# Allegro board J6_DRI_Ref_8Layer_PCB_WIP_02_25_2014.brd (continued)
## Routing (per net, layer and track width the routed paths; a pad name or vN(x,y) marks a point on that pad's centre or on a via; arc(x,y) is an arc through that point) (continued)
H_DDR2_A14: length 84
  TOP w0.102: U52.R22 v1(67.08,53.27)
  TOP w0.127: TP2MB25.1 96.7,19.1 97.16,19.1 97.38,19.33 U69.N7 ; TP2MA25.1 82.35,19.1 82.8,19.1 83.03,19.33 U68.N7 ; RN7.4 v1(104.3,19.07)
  L3-SIGNAL w0.114: v1(104.3,19.07) 103.64,19.07 103.25,19.46 102.61,19.46 102.28,19.12 96.68,19.12 TP2MB25.1 95.17,19.51 94.97,19.71 93.57,19.71 93.45,19.59 92.18,19.59 91.71,19.12 82.33,19.12 TP2MA25.1
  L6-SIGNAL w0.102: v2(70.26,24.46) 72.34,24.46 72.85,23.95 72.85,23.24 73.08,23.01 74.62,23.01 75.57,22.06 75.57,21.23 75.72,21.08 76.61,21.08 76.72,20.98 76.72,20.75 76.82,20.65 77.02,20.65 77.12,20.75 77.12,20.98 77.22,21.08 78.37,21.08 78.66,20.78 80.04,20.78 81.31,19.51 TP2MA25.1
  BOTTOM w0.102: 67.04,50.17 66.98,50.1 66.98,48.76 66.8,48.58
  BOTTOM w0.127: 66.8,48.58 66.8,47.08 66.62,46.9 66.62,41.28 67.77,40.13 67.77,38.64 70.82,35.59 70.82,32.46 70.69,32.34 70.43,32.34 70.31,32.21 70.31,31.45 70.43,31.32 70.69,31.32 70.82,31.19 70.82,29.03 70.69,28.91 70.38,28.91 70.26,28.78 v2(70.26,24.46) ; v1(67.08,53.27) 67.08,52.66 67.04,52.62 67.04,50.17 ; TP2MB25.1 95.4,19.51 94.18,20.73 U115.N7 ; U116.N7 79.83,20.73 81.05,19.51 TP2MA25.1
H_DDR2_A15: length 78.5
  TOP w0.102: U52.U22 v1(65.53,53.25)
  TOP w0.127: TP2MA12.1 81.57,24.32 82.97,24.32 U68.J7 ; TP2MB12.1 95.92,24.32 97.32,24.32 U69.J7 ; RN3.3 v1(103.66,26.5)
  L3-SIGNAL w0.114: v1(65.53,53.25) 65.94,52.84 65.94,50.61 65.7,50.37 65.43,50.37 65.18,50.12 65.18,48.95 65.43,48.69 65.43,40.72 65.3,40.59 64.52,40.59 64.19,40.26 64.19,37.19 64.41,36.97 64.41,36.11 64.16,35.86 64.16,35.31 64.39,35.08 64.39,34.32 64.55,34.16 64.71,34.16 64.88,34.33 65.05,34.33 65.21,34.17 65.21,34.01 65.03,33.84 65.03,33.68 65.48,33.23 65.48,32.6 65.67,32.41 66.22,32.41 66.4,32.24 66.4,31.3 67.02,30.67 68.76,30.67 71.75,27.68 71.75,25.91 73.46,24.21 73.79,24.21 74.3,23.7 77.25,23.7 77.5,23.46 80.64,23.46 80.89,23.71 81.24,23.71 81.56,24.03 TP2MA12.1 81.89,24.34 81.9,24.33 82.68,24.33 83.03,24.67 84.68,24.67 85.11,25.1 92.02,25.1 92.58,24.54 95.2,24.54 95.4,24.34 TP2MB12.1 96.29,24.34 96.3,24.33 100.22,24.33 102.39,26.5 v1(103.66,26.5)
  BOTTOM w0.127: TP2MB12.1 95.55,24.34 95.34,24.55 94.48,24.55 U115.J7 ; U116.J7 80.1,24.53 81.01,24.53 81.2,24.34 TP2MA12.1
H_DDR2_BA0: length 82.3
  TOP w0.102: U52.U23 v1(65.52,52.45)
  TOP w0.127: U68.J2 79.43,24.65 80.23,24.65 TP2MA10.1 ; U69.J2 93.78,24.65 94.58,24.65 TP2MB10.1
  L3-SIGNAL w0.114: v2(65.86,33.61) 68.78,33.61 69.1,33.29 70.75,33.29 71.2,32.84 73.23,32.84 73.36,32.72 73.36,32.16 73.23,32.04 72.84,32.04 72.72,31.92 72.72,31.75 72.84,31.63 73.25,31.63 73.36,31.53 73.36,31.32 73.25,31.22 73.09,31.22 72.97,31.1 72.97,30.94 73.09,30.82 73.25,30.82 73.36,30.71 73.36,30.51 73.25,30.41 72.92,30.41 72.8,30.29 72.8,30.12 72.92,30 73.25,30 73.36,29.9 73.36,27.84 75.84,25.35 78.08,25.35 78.35,25.08 79.66,25.08 79.77,24.97 TP2MA10.1 80.8,24.96 81.6,24.96 81.74,25.1 84.03,25.1 84.06,25.07 84.45,25.07 84.73,25.35 92.39,25.35 92.77,24.97 TP2MB10.1 95.19,24.93 96.18,24.93 96.35,25.1 97.61,25.1 97.64,25.07 100.3,25.07 102.23,27 v1(103.02,27)
  BOTTOM w0.102: U116.J2 83.43,24.67 82.82,24.67 82.36,25.12 81.84,25.12 81.62,24.91 TP2MA10.1 ; 64.8,48.22 64.8,49.98 64.87,50.05 64.87,51.23 ; TP2MB10.1 95.97,24.91 96.19,25.12 96.71,25.12 97.17,24.67 97.78,24.67 U115.J2
  BOTTOM w0.127: v1(65.52,52.45) 65.1,52.02 65.1,51.46 64.87,51.23 ; 64.8,48.22 64.67,48.1 64.67,45.77 64.19,45.28 64.19,37.2 64.44,36.95 64.44,35.8 64.16,35.52 64.16,35.21 64.54,34.83 64.54,33.78 64.72,33.61 v2(65.86,33.61) ; v1(103.02,27) 103.72,27 104.13,27.4 104.47,27.4 104.87,27 RN12.3
H_DDR2_BA1: length 83.8
  TOP w0.127: U68.K8 83.44,23.85 82.73,23.85 82.54,24.04 81.89,24.04 81.75,23.9 81.41,23.9 81.2,24.11 TP2MA13.1 ; U52.U27 64.78,48.5 64.78,44.07 64.95,43.9 64.95,38.38 64.21,37.65 64.21,37.11 64.49,36.83 64.49,36.49 64.72,36.26 64.72,36.09 64.6,35.97 63.3,35.97 63.2,35.87 63.2,35.67 63.3,35.56 64.59,35.56 64.72,35.44 64.72,35.21 64.62,35.11 63.3,35.11 63.2,35.01 63.2,34.8 63.37,34.62 63.37,33.81 63.55,33.63 64.31,33.63 64.44,33.76 64.44,34.57 64.57,34.7 64.82,34.7 64.95,34.57 64.95,34.24 65.07,34.11 66.24,34.11 66.37,33.99 66.37,33.1 66.5,32.97 v2(67.34,32.97) ; U69.K8 97.79,23.85 97.08,23.85 96.88,24.06 96.26,24.06 96.1,23.9 95.76,23.9 95.55,24.11 TP2MB13.1
  L3-SIGNAL w0.114: TP2MA13.1 79.12,24.11 78.89,24.34 75.4,24.34 74.77,24.97 74.77,25.21 72.34,27.64 72.34,27.9 70.85,29.4 70.85,29.56 70.98,29.7 70.98,29.86 70.82,30.02 70.66,30.02 70.52,29.88 70.36,29.88 70.2,30.04 70.2,30.21 70.34,30.34 70.34,30.5 70.17,30.67 70.01,30.67 69.88,30.53 69.71,30.53 68.92,31.32 68.56,31.32 68.4,31.16 67.75,31.16 67.51,31.4 67.51,32.08 67.34,32.26 v2(67.34,32.97)
  L6-SIGNAL w0.102: TP2MA13.1 81.25,24.11 81.4,23.95 81.74,23.95 82.02,24.24 85.2,24.24 85.2,24.23 85.7,24.23 86.11,23.83 87.96,23.83 88.49,24.36 90.93,24.36 91.85,23.45 93.32,23.45 93.98,24.11 TP2MB13.1 95.35,23.83 96.04,23.83 96.24,24.03 98.22,24.03 98.43,24.24 99.79,24.24 100.53,23.5 101.98,23.5 102.21,23.27 102.25,23.27 v1(103.02,22.5)
  BOTTOM w0.127: RN14.2 104.3,23.07 103.72,22.5 v1(103.02,22.5) ; TP2MB13.1 94.51,24.08 94.28,23.85 93.78,23.85 U115.K8 ; TP2MA13.1 80.16,24.08 79.93,23.85 79.43,23.85 U116.K8
H_DDR2_BA2: length 77.2
  TOP w0.102: U52.U26 v1(65.59,49.26)
  TOP w0.127: U68.J3 80.27,24.26 80.54,24.53 81.04,24.53 81.46,24.95 81.97,24.95 TP2MA11.1 ; U69.J3 94.62,24.26 94.89,24.53 95.39,24.53 95.81,24.95 96.32,24.95 TP2MB11.1
  L3-SIGNAL w0.114: TP2MA11.1 82.19,24.72 81.35,24.72 81.15,24.53 79.46,24.53 79.27,24.72 78,24.72 77.88,24.84 75.72,24.84 72.85,27.71 72.85,29.29 72.72,29.42 72.34,29.42 72.21,29.54 72.21,30.42 72.11,30.52 71.26,30.52 71.15,30.64 71.15,30.81 71.26,30.93 72.11,30.93 72.21,31.03 72.21,31.23 72.11,31.33 71.57,31.33 71.45,31.45 71.45,31.62 71.57,31.74 72.11,31.74 72.21,31.84 72.21,32.08 71.96,32.34 70.82,32.34 70.43,32.72 70.21,32.72 70.1,32.62 70.1,31.55 70,31.45 69.8,31.45 69.7,31.55 69.7,32.62 69.6,32.72 68.91,32.72 68.66,32.97 68.28,32.97 68.02,32.72 v2(68.02,32.34)
  L6-SIGNAL w0.102: TP2MA11.1 83.08,24.72 83.13,24.67 84.94,24.67 85.14,24.87 86.64,24.87 87.17,24.34 87.86,24.34 88.44,24.92 92.15,24.92 92.48,24.59 93.49,24.59 93.59,24.69 93.59,24.79 93.69,24.89 93.9,24.89 94,24.79 94,24.69 94.1,24.59 95.53,24.59 95.66,24.72 TP2MB11.1 101.35,24.72 101.73,24.34 102.16,24.34 102.39,24.56 v1(103.02,24.56)
  BOTTOM w0.127: RN14.4 104.87,24.14 104.44,24.56 v1(103.02,24.56) ; v2(68.02,32.34) 68.02,33.43 66.7,34.75 66.7,36.65 65.81,37.54 65.81,39.58 65.1,40.29 65.1,44.65 65.47,45.02 65.47,47.56 65.59,47.69 v1(65.59,49.26) ; TP2MA11.1 82.65,24.26 U116.J3 ; TP2MB11.1 97,24.26 U115.J3
H_DDR2_CASN: length 82.5
  TOP w0.127: TP2MA6.1 81.1,26.29 80.49,26.29 80.06,25.86 U68.G3 ; U52.U28 65.13,44.95 65.2,44.87 65.2,36.55 65.74,36.02 65.74,35.41 66.81,34.33 66.81,33.85 66.93,33.73 67.1,33.73 67.22,33.85 67.22,34.76 67.34,34.88 67.51,34.88 67.63,34.76 67.63,33.85 67.74,33.73 67.91,33.73 68.03,33.85 68.03,34.76 68.15,34.88 68.32,34.88 68.44,34.76 68.44,32.84 68.56,32.72 68.73,32.72 68.84,32.84 68.84,34.76 68.96,34.88 69.13,34.88 69.25,34.76 69.25,32.84 69.37,32.72 69.54,32.72 69.66,32.84 69.66,34.52 69.76,34.62 69.93,34.62 70.05,34.75 v2(70.05,35.13) ; U69.G3 94.45,25.86 94.87,26.28 95.44,26.28 TP2MB6.1
  L3-SIGNAL w0.114: v2(70.05,35.13) 70.86,35.13 70.97,35.25 70.97,35.33 71.09,35.45 71.31,35.45 71.43,35.33 71.43,35.25 71.54,35.13 72.62,35.13 72.74,35.25 72.74,35.37 72.85,35.49 73.08,35.49 73.19,35.37 73.19,35.25 73.31,35.13 74.75,35.13 75.13,34.75 75.13,28.86 76.23,27.76 76.23,27.47 77.38,26.32 80.04,26.32 80.09,26.27 81.08,26.27 TP2MA6.1
  L6-SIGNAL w0.102: TP2MA6.1 82.4,26.49 82.6,26.29 82.85,26.29 83.06,26.49 83.34,26.49 83.57,26.27 85.7,26.27 85.83,26.39 85.83,26.62 86.11,26.9 86.61,26.9 86.89,26.62 86.89,26.39 87.02,26.27 88.33,26.27 88.35,26.24 93.37,26.24 93.83,26.7 94.39,26.7 94.51,26.57 94.51,26.44 94.64,26.32 95.18,26.32 TP2MB6.1 96.6,26.49 96.88,26.22 100.56,26.22 100.71,26.06 101.35,26.06 101.5,26.22 102.73,26.22 v1(103.02,25.93)
  BOTTOM w0.127: TP2MB6.1 96.55,26.49 97.1,25.94 97.31,25.94 U115.G3 ; v1(103.02,25.93) 103.72,25.93 104.3,26.5 RN12.2 ; TP2MA6.1 82.19,26.49 82.75,25.94 82.96,25.94 U116.G3
H_DDR2_CKE: length 89
  TOP w0.102: U52.U24 v1(65.56,51.68)
  TOP w0.127: TP2MA1.1 81.13,27.97 82.37,27.97 82.68,27.66 82.68,27.25 82.88,27.05 83.29,27.05 83.41,26.93 83.41,26.52 83.67,26.27 84.23,26.27 U68.G9 ; TP2MB1.1 95.48,27.97 96.72,27.97 97.03,27.66 97.03,27.25 97.23,27.05 97.64,27.05 97.76,26.93 97.76,26.52 98.02,26.27 98.58,26.27 U69.G9
  L6-SIGNAL w0.102: v2(105.18,28.4) 104.7,28.88 100.71,28.88 99.97,28.15 98.2,28.15 97.75,28.59 95.95,28.59 TP2MB1.1 93.52,28.04 93.32,28.25 91.54,28.25 91.26,28.53 85.5,28.53 85.22,28.25 82.78,28.25 82.25,28.78 81.41,28.78 81.05,28.43 TP2MA1.1 79.45,28.04 79.25,28.25 77.52,28.25 76.86,28.91 76.86,29.7 76.53,30.03 76,30.03 75.77,30.25 75.77,31.63 74.9,32.49 74.33,32.49 74.18,32.64 74.18,32.79 74.03,32.93 73.89,32.93 73.71,32.76 73.57,32.76 73.43,32.9 73.43,33.04 73.6,33.22 73.6,33.36 73.46,33.51 73.31,33.51 73.14,33.33 73,33.33 72.85,33.48 72.85,33.62 73.03,33.79 73.03,33.94 72.88,34.08 72.74,34.08 72.56,33.91 72.42,33.91 72.28,34.05 72.28,34.19 72.45,34.37 72.45,34.51 72.31,34.66 72.16,34.66 71.99,34.48 71.85,34.48 71.7,34.63 71.7,34.77 71.88,34.94 71.88,35.09 71.73,35.23 71.59,35.23 70.92,34.56 70.75,34.56 70.63,34.68 70.63,34.85 71.3,35.52 71.3,35.66 71.16,35.81 71.01,35.81 70.72,35.52 70.56,35.52 70.44,35.64 70.44,35.8 70.72,36.09 70.72,36.24 70.58,36.38 70.44,36.38 70.09,36.03 69.92,36.03 69.8,36.15 69.8,36.32 70.15,36.67 70.15,37.28 70.02,37.42 v2(64.67,37.42)
  BOTTOM w0.102: 65.16,51.02 65.16,49.89 65.01,49.73 65.01,48.8 65.06,48.75
  BOTTOM w0.127: U116.G9 78.61,26.24 79.2,26.24 79.45,26.49 79.45,26.85 79.65,27.05 80.06,27.05 TP2MA1.1 ; RN12.4 105.18,27.69 v2(105.18,28.4) ; 65.16,51.02 65.56,51.41 v1(65.56,51.68) ; v2(64.67,37.42) 64.67,39.32 64.49,39.5 64.49,45.08 64.94,45.52 64.94,47.95 65.06,48.07 65.06,48.75 ; TP2MB1.1 94.41,27.05 94.01,27.05 93.8,26.85 93.8,26.49 93.55,26.24 92.96,26.24 U115.G9
H_DDR2_CLK0: length 73.2
  TOP w0.089: TP2MB4.1 96.67,26.65 96.74,26.65 97.06,26.33 97.32,26.33 97.38,26.39 U69.F7 ; TP2MA4.1 82.32,26.65 82.39,26.65 82.71,26.33 82.97,26.33 83.03,26.39 U68.F7 ; v2(69.24,36.53) 68.94,36.53 68.81,36.4 68.81,36.16 68.68,36.03 67.12,36.03 66.51,36.64 66.51,37.31 66.61,37.4 67.91,37.4 67.91,37.4 68.13,37.4 68.13,37.4 68.23,37.4 68.52,37.69 68.52,38.44 68.13,38.83 66.15,38.83 65.8,39.18 65.8,46.7 65.8,47.62 65.93,47.75 U52.T28
  L3-SIGNAL w0.076: v2(69.24,36.53) 69.63,36.53 69.71,36.45 69.71,36.34 70.02,36.03 70.02,35.99 75.06,35.99 75.82,35.23 75.82,34.77 75.83,34.76 75.83,34.75
  L3-SIGNAL w0.102: 75.83,34.75 75.83,29.01 76.57,28.27 77.52,28.27 78.71,27.08 80.69,27.08 80.74,27.13 81.57,27.13 81.59,27.1 81.86,27.1 TP2MA4.1 82.37,26.6 85.47,26.6 86,27.13 87.07,27.13 87.63,26.57 93.6,26.57 94.32,27.29 94.81,27.29 94.97,27.13 96.19,27.13 TP2MB4.1 96.49,26.98 97.59,26.98 98.48,27.87 99.19,27.87 100.28,28.96 102.88,28.96 103.19,29.27 103.19,29.61 v2(103.76,30.18)
  BOTTOM w0.089: v2(103.76,30.18) 104.93,30.18 R685.1 ; U115.F7 94.4,26.66 94.89,27.16 95.3,27.16 95.55,26.9 TP2MB4.1 ; U116.F7 80.05,26.66 80.54,27.16 80.95,27.16 81.2,26.9 TP2MA4.1
H_DDR2_CLK0N: length 75.5
  TOP w0.089: v2(69.24,35.77) 67.01,35.77 66.24,36.53 66.24,37.42 66.5,37.67 68.12,37.67 68.25,37.8 68.25,38.33 68.02,38.56 66.04,38.56 65.53,39.07 65.53,46.59 65.53,46.59 65.53,48.19 65.93,48.59 U52.T27 ; TP2MA5.1 80.89,26.9 81.47,26.9 81.99,26.38 82.28,26.38 82.6,26.06 82.83,26.06 U68.G7 ; U69.G7 97.18,26.06 96.95,26.06 96.63,26.38 96.35,26.38 95.82,26.9 95.24,26.9 TP2MB5.1
  L3-SIGNAL w0.076: v2(69.24,35.77) 74.96,35.77 75.59,35.14 75.59,34.76 75.58,34.75
  L3-SIGNAL w0.102: v2(103.78,29.29) 103.57,29.29 102.98,28.7 100.38,28.7 99.29,27.61 98.58,27.61 97.69,26.72 96.78,26.72 96.58,26.52 96.17,26.52 95.81,26.88 95.2,26.88 TP2MB5.1 94.68,27.04 94.43,27.04 93.7,26.32 87.52,26.32 86.97,26.88 86.11,26.88 85.58,26.34 82,26.34 81.46,26.88 80.85,26.88 TP2MA5.1 80.57,26.8 78.63,26.8 77.42,28.02 76.46,28.02 75.58,28.9 75.58,34.75
  BOTTOM w0.089: U115.G7 93.95,25.86 93.83,25.98 93.83,26.16 93.95,26.28 94.4,26.28 94.68,26.56 94.88,26.56 TP2MB5.1 ; v2(103.78,29.29) 104.93,29.29 R688.1 ; U116.G7 79.6,25.86 79.48,25.98 79.48,26.16 79.6,26.28 80.05,26.28 80.33,26.56 80.53,26.56 TP2MA5.1
H_DDR2_CSN0: length 82.2
  TOP w0.102: U52.P24 v1(67.93,51.7)
  TOP w0.127: TP2MB8.1 94.59,25.45 93.78,25.45 U69.H2 ; U68.H2 79.43,25.45 80.19,25.45 TP2MA8.1
  L3-SIGNAL w0.114: TP2MA8.1 79.65,25.86 79.43,26.09 76.12,26.09 74.24,27.97 74.24,29.13 74.35,29.23 74.65,29.23 74.76,29.35 74.76,29.51 74.65,29.63 74.35,29.63 74.24,29.74 74.24,30.58 74.35,30.68 74.65,30.68 74.76,30.8 74.76,30.97 74.65,31.09 74.35,31.09 74.24,31.19 74.24,31.4 74.75,31.9 74.75,34.37 74.5,34.62 70.69,34.62 70.38,34.32 69.98,34.32 69.67,34.62 66.64,34.62 66.45,34.81 66.45,35.25 66.7,35.5 66.7,35.97 67.64,36.91 67.64,38.05 67.77,38.18 68.15,38.18 68.28,38.31 68.28,41.81 68.17,41.92 67.89,41.92 67.77,42.04 67.77,42.2 67.89,42.32 68.17,42.32 68.28,42.42 68.28,43.14 68.38,43.24 68.55,43.24 68.66,43.34 68.66,43.55 68.55,43.65 68.38,43.65 68.28,43.75 68.28,44.02 68.66,44.4 68.66,48.85 69,49.19 69,50.62 69.07,50.69 69.07,51.01 68.85,51.24 68.06,51.24 67.93,51.37 v1(67.93,51.7)
  L6-SIGNAL w0.102: v1(103.66,25.48) 102.59,25.48 102.23,25.84 101.45,25.84 101.44,25.83 100.89,25.83 100.89,25.84 98.78,25.84 98.76,25.86 98.42,25.86 98.18,25.63 98.18,25.59 98.17,25.58 96.34,25.58 96.06,25.86 TP2MB8.1 94.41,25.86 94.28,25.99 94.28,26.11 94.16,26.24 93.95,26.24 93.83,26.11 93.83,25.97 93.7,25.85 82.96,25.85 82.61,25.5 81.94,25.5 81.66,25.78 80.8,25.78 TP2MA8.1
  BOTTOM w0.102: TP2MB8.1 95.4,25.76 96.06,25.76 96.24,25.58 96.65,25.58 96.7,25.63 97.08,25.63 97.23,25.48 97.76,25.48 U115.H2 ; U116.H2 83.41,25.48 82.88,25.48 82.73,25.63 82.45,25.63 82.37,25.55 81.92,25.55 81.71,25.76 81.05,25.76 TP2MA8.1
  BOTTOM w0.127: RN12.1 104.87,25.93 104.43,25.48 v1(103.66,25.48)
H_DDR2_D0: length 41.1
  TOP w0.102: v1(75.19,49.25) U52.E26
  L3-SIGNAL w0.114: v2(94.89,33.86) 94.51,34.24 94.25,34.24 93.44,33.43 93.27,33.43 93.15,33.55 93.15,33.71 93.8,34.36 93.8,34.5 93.65,34.65 93.51,34.65 92.92,34.05 92.75,34.05 92.63,34.17 92.63,34.34 93.22,34.93 93.22,35.08 88.98,39.32 84.92,39.32 84.82,39.42 84.82,39.6 84.72,39.7 84.52,39.7 84.42,39.6 84.42,39.42 84.31,39.32 84.08,39.32 83.98,39.42 83.98,39.6 83.88,39.7 83.68,39.7 83.58,39.6 83.58,39.42 83.48,39.32 82.75,39.32 78,44.07 78,44.27 75.74,46.54 75.54,46.54 75.29,46.79 75.19,46.89 v1(75.19,49.25)
  BOTTOM w0.127: v2(94.89,33.86) 95.28,33.48 95.58,33.48 95.71,33.35 95.71,32.97 95.53,32.79 95.53,32.46 95.71,32.29 95.71,31.96 95.53,31.78 95.53,29.16 94.95,28.58 94.95,28.02 94.39,27.46 U115.E7
H_DDR2_D1: length 45.3
  TOP w0.127: U52.G25 v1(73.53,50.07)
  BOTTOM w0.127: v1(73.53,50.07) 73.93,49.68 73.93,49.04 75.72,47.25 78.3,47.25 78.78,46.76 78.78,46.12 79.04,45.86 79.64,45.86 80.1,45.41 80.1,44.14 81.61,42.62 89.38,42.62 90.65,41.35 97.1,41.35 99.26,39.19 99.26,37.97 99.53,37.69 99.53,37 99.9,36.64 99.9,28.5 99.31,27.92 98.53,27.92 U115.D2
H_DDR2_D2: length 40
  TOP w0.102: U52.F25 v1(74.31,50.05)
  L3-SIGNAL w0.102: 73.93,49.47 74.13,49.67 v1(74.31,50.05)
  L3-SIGNAL w0.114: 73.93,49.47 73.93,46.17 76.1,44 76.3,44 83.01,37.29 87.71,37.29 88.03,36.96 88.03,36.82 87.73,36.52 87.73,36.38 87.88,36.23 88.02,36.23 88.32,36.53 88.46,36.53 88.61,36.39 88.61,36.25 88.23,35.87 88.23,35.7 88.35,35.58 88.52,35.58 88.9,35.96 89.04,35.96 89.18,35.81 89.18,35.67 88.81,35.29 88.81,35.12 88.92,35 89.09,35 89.47,35.38 89.61,35.38 90.58,34.42 90.58,33.61 90.7,33.48 91.52,33.48 91.64,33.35 91.64,33.15 91.54,33.05 91.11,33.05 91.01,32.95 91.01,32.74 91.11,32.64 91.54,32.64 91.64,32.54 91.64,29.92 91.52,29.8 90.88,29.8 v1(90.78,29.9)
  BOTTOM w0.127: v1(90.78,29.9) 91.31,29.9 91.74,29.47 92.98,29.47 U115.C8
H_DDR2_D3: length 40
  TOP w0.102: v1(74.35,50.85) 73.95,51.25 U52.F24
  L3-SIGNAL w0.102: 74.73,48.76 74.73,49.87 74.7,49.89 74.7,50.51 v1(74.35,50.85)
  L3-SIGNAL w0.114: v2(91.97,35.13) 91.97,35.61 91.58,36 91.39,36 91.09,35.7 90.92,35.7 90.8,35.82 90.8,35.99 91.1,36.29 91.1,36.43 88.72,38.81 88.42,38.81 88.21,38.61 87.99,38.61 87.78,38.81 82.63,38.81 77.24,44.2 77.24,44.63 75.79,46.08 75.36,46.08 74.73,46.71 74.73,48.76
  BOTTOM w0.127: v2(91.97,35.13) 91.97,34.37 92.1,34.24 94.06,34.24 94.18,34.11 94.18,33.86 94.12,33.8 94.12,33.67 94.56,33.23 94.69,33.23 94.82,33.1 94.82,32.46 95.15,32.13 95.15,29.42 94.61,28.88 94.61,28.12 94.36,27.87 94.08,27.87 93.68,27.46 U115.E8
H_DDR2_D4: length 41.1
  TOP w0.102: U52.F26 73.99,49.6 v1(74.35,49.29)
  L3-SIGNAL w0.102: 93.17,32.79 93.88,32.79
  L3-SIGNAL w0.114: v1(74.35,49.29) 74.35,46.13 76.15,44.33 76.56,44.33 82.58,38.31 83.72,38.31 83.82,38.2 83.82,37.9 83.92,37.8 84.13,37.8 84.23,37.9 84.23,38.2 84.33,38.31 84.53,38.31 84.64,38.2 84.64,37.9 84.74,37.8 84.94,37.8 85.04,37.9 85.04,38.2 85.14,38.31 85.35,38.31 85.45,38.2 85.45,37.9 85.55,37.8 85.75,37.8 85.85,37.9 85.85,38.2 85.96,38.31 86.16,38.31 86.26,38.2 86.26,37.9 86.36,37.8 86.57,37.8 86.67,37.9 86.67,38.2 86.77,38.31 87.66,38.31 88.02,37.94 88.17,37.94 88.45,38.23 88.62,38.23 88.74,38.11 88.74,37.94 88.45,37.65 88.45,37.51 88.6,37.36 88.74,37.36 89.04,37.67 89.21,37.67 89.33,37.55 89.33,37.38 89.03,37.08 89.03,36.93 89.17,36.79 89.32,36.79 89.57,37.04 89.73,37.04 89.85,36.92 89.85,36.75 89.6,36.5 89.6,36.36 89.77,36.2 89.91,36.2 90.11,36.4 90.25,36.4 90.4,36.25 90.4,36.11 90.2,35.91 90.2,35.76 92.38,33.58 92.38,33.43 92.22,33.27 92.22,33.1 92.34,32.98 92.51,32.98 92.67,33.15 92.81,33.15 93.17,32.79 ; 93.88,32.79 v2(94.11,32.79)
  BOTTOM w0.127: U115.C7 94.77,29.64 94.77,31.19 94.54,31.42 94.54,31.57 94.67,31.7 94.67,31.85 94.53,31.99 94.39,31.99 94.25,31.85 94.11,32 v2(94.11,32.79)
H_DDR2_D5: length 48.4
  TOP w0.127: v2(92.28,38.05) 92.53,37.8 92.53,36.65 92.41,36.53 92.02,36.53 91.92,36.63 91.92,37.42 91.8,37.54 91.64,37.54 91.52,37.42 91.52,36.63 91.41,36.53 91.21,36.53 91.11,36.63 91.11,37.42 90.99,37.54 90.82,37.54 90.7,37.42 90.7,36.63 90.6,36.53 90.37,36.53 90.25,36.65 90.25,37.54 90.12,37.67 89.87,37.67 89.76,37.77 89.76,38.33 89.66,38.43 89.46,38.43 89.36,38.33 89.36,37.77 89.26,37.67 89.05,37.67 88.95,37.77 88.95,38.33 88.85,38.43 88.65,38.43 88.54,38.33 88.54,37.77 88.44,37.67 88.21,37.67 88.09,37.8 88.09,38.31 87.96,38.43 87.4,38.43 86.54,39.29 82.68,43.16 76.63,43.16 74.34,45.45 74.34,48.44 U52.F27
  BOTTOM w0.127: v2(92.28,38.05) 92.28,36.78 93.29,35.77 93.68,35.77 93.8,35.64 93.8,35 93.93,34.88 94.44,34.88 94.82,34.5 95.07,34.5 95.43,34.14 95.58,34.14 96.14,33.58 96.14,32.51 96.39,32.26 96.39,32.01 95.94,31.55 95.94,28.93 95.78,28.78 95.78,28.48 95.94,28.32 96.75,28.32 97.31,27.76 97.31,27.54 U115.E3
H_DDR2_D6: length 46.3
  TOP w0.127: v2(96.47,38.81) 96.47,37.54 96.34,37.42 96.01,37.42 95.89,37.54 95.89,39.45 95.76,39.58 95.55,39.58 95.45,39.47 95.45,38.92 95.35,38.81 95.15,38.81 95.05,38.92 95.05,39.47 94.95,39.58 94.74,39.58 94.64,39.47 94.64,38.92 94.54,38.81 94.31,38.81 93.68,39.45 87.66,39.45 83.39,43.72 76.86,43.72 75.16,45.42 75.16,48.43 U52.E27
  BOTTOM w0.102: 98.12,31.57 98.12,31.4
  BOTTOM w0.127: 98.12,31.57 98.12,35.56 98.63,36.07 98.63,36.71 98.53,36.81 98.35,36.81 98.25,36.91 98.25,37.11 98.35,37.21 98.53,37.21 98.63,37.32 98.63,37.54 98.5,37.67 97.99,37.67 97.87,37.8 97.87,38.31 97.71,38.46 97.26,38.46 97.13,38.59 97.13,38.76 97.13,38.9 97.13,39.04 96.85,39.32 96.6,39.32 96.47,39.19 v2(96.47,38.81) ; U115.C2 97.79,29.45 97.79,31.07 98.12,31.4
H_DDR2_D7: length 48.3
  TOP w0.127: 74.73,48.05 74.88,47.91 74.88,45.29 76.73,43.44 83.03,43.44 87.53,38.94 90.18,38.94 90.28,38.84 90.28,38.15 90.38,38.05 90.58,38.05 90.69,38.15 90.69,38.84 90.79,38.94 90.99,38.94 91.09,38.84 91.09,38.15 91.19,38.05 91.4,38.05 91.5,38.15 91.5,38.84 91.6,38.94 91.83,38.94 91.93,38.84 91.93,38.79 92.03,38.69 92.24,38.69 92.34,38.79 92.34,38.84 92.44,38.94 92.64,38.94 92.74,38.84 92.74,38.79 92.85,38.69 93.05,38.69 93.15,38.79 93.15,38.84 93.25,38.94 93.55,38.94 93.79,38.7 93.79,38.56 93.68,38.45 93.68,38.3 93.82,38.16 93.96,38.16 94.07,38.27 94.31,38.27 94.44,38.14 94.44,35.64 94.56,35.51 94.82,35.51 94.95,35.64 94.95,38.18 95.07,38.31 95.33,38.31 95.45,38.18 95.45,37.04 95.58,36.91 96.93,36.91 97.05,37.04 v2(97.05,37.92)
  BOTTOM w0.127: v2(97.05,37.92) 97.69,37.29 97.69,31.57 96.93,30.81 96.93,30.32 U115.B3
H_DDR2_D8: length 46.3
  TOP w0.102: v1(71.94,51.7) U52.H23
  TOP w0.127: U69.E3 94.23,27.51 94.45,27.51 94.96,28.02 94.96,28.34 95.2,28.58 95.66,28.58 95.78,28.7 95.78,32.18 95.89,32.29 95.99,32.29 96.11,32.41 96.11,32.57 95.99,32.69 95.89,32.69 95.78,32.79 95.78,33 95.89,33.1 96.01,33.1 96.11,33.2 96.11,33.4 96.01,33.51 95.89,33.51 95.78,33.61 95.78,33.84 96.04,34.09 96.04,34.36 95.94,34.46 95.75,34.46 95.63,34.58 95.63,34.75 95.75,34.87 95.94,34.87 96.04,34.97 v2(96.04,35.38)
  BOTTOM w0.127: v1(71.94,51.7) 71.94,51.32 71.99,51.27 71.99,48.91 75.48,45.43 75.48,45 76.24,44.24 77.2,44.24 81.36,40.08 87.96,40.08 88.98,39.07 94.23,39.07 94.34,38.97 94.34,38.53 94.44,38.43 94.64,38.43 94.74,38.53 94.74,38.97 94.84,39.07 95.07,39.07 95.2,38.94 95.2,37.67 96.04,36.83 v2(96.04,35.38)
H_DDR2_D9: length 46.6
  TOP w0.102: v1(72.75,50.82) U52.H25
  TOP w0.127: v2(96.55,36.27) 96.55,34.87 96.65,34.77 96.98,34.77 97.08,34.67 97.08,34.47 96.98,34.36 96.65,34.36 96.55,34.26 96.55,34.06 96.65,33.96 96.98,33.96 97.08,33.86 97.08,33.65 96.98,33.55 96.65,33.55 96.55,33.45 96.55,33.25 96.65,33.14 96.86,33.14 96.98,33.03 96.98,32.86 96.86,32.74 96.65,32.74 96.55,32.64 96.55,32.21 96.16,31.83 96.16,28.78 96.29,28.65 96.7,28.65 96.83,28.53 96.83,28.3 97.31,27.82 97.31,27.54 U69.E7
  BOTTOM w0.127: v1(72.75,50.82) 72.29,50.36 72.29,49.02 75.7,45.61 77.15,45.61 78.03,44.73 78.03,43.92 81.36,40.59 88.32,40.59 88.44,40.46 88.44,40.21 88.58,40.07 88.73,40.07 88.93,40.27 89.07,40.27 89.21,40.13 89.21,39.98 89.01,39.78 89.01,39.64 89.2,39.45 95.45,39.45 95.58,39.32 95.58,37.92 96.55,36.96 v2(96.55,36.27)
H_DDR2_D10: length 46.7
  TOP w0.127: v1(72.75,51.64) U52.H24 ; U69.E8 98.18,27.47 98.58,27.87 99.44,27.87 100.08,28.5 100.08,37.49 v2(98.25,39.32)
  BOTTOM w0.102: 77.75,46.79 77.51,47.03 75.58,47.03 ; 73.15,49.86 73.15,51.23
  BOTTOM w0.127: 73.15,51.23 v1(72.75,51.64) ; 73.15,49.86 73.56,49.46 73.56,49.05 75.58,47.03 ; 77.75,46.79 77.9,46.64 77.9,46.64 78.83,45.71 78.83,44.64 81.36,42.12 89.26,42.12 90.4,40.97 96.6,40.97 v2(98.25,39.32)
H_DDR2_D11: length 46.2
  TOP w0.102: v1(72.76,49.23) U52.H26
  TOP w0.127: U69.C7 97.21,29.24 97,29.24 96.82,29.06 96.67,29.06 96.55,29.19 96.55,29.44 96.77,29.67 96.77,29.85 96.55,30.08 96.55,31.09 96.8,31.34 96.8,31.49 96.66,31.62 96.66,31.79 96.78,31.91 96.95,31.91 97.08,31.77 97.23,31.77 97.49,32.03 97.49,34.95 v2(97.05,35.38)
  BOTTOM w0.127: v1(72.76,49.23) 72.76,48.96 75.86,45.86 77.53,45.86 78.32,45.07 78.32,44.13 81.36,41.1 88.7,41.1 89.08,40.72 89.36,40.72 89.64,40.44 89.64,39.96 89.76,39.83 89.99,39.83 90.09,39.93 90.09,40.11 90.2,40.21 90.4,40.21 90.5,40.11 90.5,39.93 90.6,39.83 90.81,39.83 90.91,39.93 90.91,40.11 91.01,40.21 91.21,40.21 91.31,40.11 91.31,39.93 91.41,39.83 91.62,39.83 91.72,39.93 91.72,40.11 91.82,40.21 92.02,40.21 92.13,40.11 92.13,39.93 92.23,39.83 92.43,39.83 92.53,39.93 92.53,40.11 92.63,40.21 92.84,40.21 92.94,40.11 92.94,39.93 93.04,39.83 93.24,39.83 93.34,39.93 93.34,40.11 93.45,40.21 93.65,40.21 93.75,40.11 93.75,39.93 93.85,39.83 94.06,39.83 94.16,39.93 94.16,40.11 94.26,40.21 94.46,40.21 94.56,40.11 94.56,39.93 94.67,39.83 94.87,39.83 94.97,39.93 94.97,40.11 95.07,40.21 95.28,40.21 95.38,40.11 95.38,39.93 95.48,39.83 95.96,39.83 96.09,39.7 96.09,39.35 95.96,39.22 95.96,38.33 96.09,38.2 96.37,38.2 96.52,38.05 96.52,37.62 97.26,36.88 97.26,36.15 97.05,35.94 v2(97.05,35.38)
H_DDR2_D12: length 46.3
  TOP w0.102: v1(72.77,50.07) U52.G26
  TOP w0.127: U69.C8 97.79,29.45 97.79,31.12 98.45,31.78 98.45,34.24 98.63,34.42 98.63,34.78 98.45,34.95 98.45,35.24 98.55,35.35 99.19,35.35 99.31,35.46 99.31,35.63 99.19,35.75 98.55,35.75 98.45,35.85 98.45,36.06 98.55,36.16 99.17,36.16 99.29,36.28 99.29,36.45 99.17,36.56 98.55,36.56 98.45,36.67 98.45,36.87 98.55,36.97 99.17,36.97 99.29,37.09 99.29,37.26 99.17,37.38 98.58,37.38 98.45,37.5 v2(98.45,38.31)
  BOTTOM w0.127: v1(72.77,50.07) 72.77,49.84 73.18,49.43 73.18,49 75.37,46.8 77.3,46.8 78.58,45.53 78.58,44.39 81.36,41.61 89.1,41.61 90.12,40.59 96.16,40.59 v2(98.45,38.31)
H_DDR2_D13: length 44.5
  TOP w0.102: v1(70.98,49.95) U52.J25
  TOP w0.127: v2(91.08,33.99) 91.21,33.86 92.66,33.86 93.04,33.48 93.04,31.96 93.78,31.22 93.78,30.27 U69.B3
  BOTTOM w0.127: v2(91.08,33.99) 91.08,34.37 90.96,34.5 90.22,34.5 90.09,34.62 90.09,34.85 90.2,34.95 90.84,34.95 90.96,35.07 90.96,35.24 90.84,35.36 90.2,35.36 90.09,35.46 90.09,35.82 89.97,35.94 89.81,35.94 89.69,35.82 89.69,35.54 89.55,35.4 89.22,35.4 88.85,35.77 88.85,36.58 88.95,36.68 90.25,36.68 90.37,36.8 90.37,36.97 90.25,37.09 88.92,37.09 88.8,37.21 88.8,37.37 88.92,37.49 90.25,37.49 90.37,37.61 90.37,37.78 90.25,37.9 88.95,37.9 87.78,39.07 81.36,39.07 76.76,43.67 76,43.67 74.97,44.69 74.97,45.2 71.36,48.81 71.36,49.57 v1(70.98,49.95)
H_DDR2_D14: length 46.6
  TOP w0.102: v1(70.95,49.34) U52.J26
  TOP w0.127: U69.C2 92.98,29.47 92.23,29.47 91.61,30.09 91.61,31.9 91.26,32.25 91.26,33.28 90.96,33.58 90.47,33.58 v2(90.07,33.99)
  BOTTOM w0.127: v2(90.07,33.99) 89.48,33.99 89.36,34.11 89.36,34.62 89.23,34.75 88.95,34.75 88.67,35.03 88.01,35.03 87.88,35.16 87.88,35.44 88.47,36.02 88.47,36.65 88.06,37.06 88.06,38.15 87.66,38.56 86.72,38.56 86.62,38.46 86.62,38.35 86.5,38.23 86.33,38.23 86.21,38.35 86.21,38.46 86.11,38.56 85.91,38.56 85.81,38.46 85.81,37.15 85.69,37.04 85.52,37.04 85.4,37.15 85.4,38.46 85.3,38.56 85.07,38.56 84.97,38.46 84.97,36.9 84.85,36.78 84.68,36.78 84.56,36.9 84.56,38.46 84.46,38.56 84.26,38.56 84.16,38.46 84.16,37.08 84.04,36.96 83.87,36.96 83.75,37.08 83.75,38.46 83.65,38.56 81.36,38.56 76.5,43.41 75.87,43.41 74.68,44.61 74.68,45.04 73.23,46.48 71.86,46.48 70.95,47.4 70.95,49.15 70.95,49.16 v1(70.95,49.34)
H_DDR2_D15: length 45.7
  TOP w0.102: v1(71.12,50.83) U52.J24
  TOP w0.127: v2(95.53,36.27) 95.53,35.59 95.15,35.21 95.15,34.32 95.4,34.06 95.4,29.35 94.64,28.59 94.64,28.15 94.36,27.86 93.78,27.86 U69.D2
  BOTTOM w0.127: v1(71.12,50.83) 71.65,50.28 71.65,48.87 73.48,47.04 73.49,47.04 75.22,45.31 75.22,44.82 76.1,43.94 76.99,43.94 81.36,39.58 87.83,39.58 89.1,38.31 89.46,38.31 89.56,38.41 89.56,38.54 89.68,38.66 89.85,38.66 89.97,38.54 89.97,38.41 90.07,38.31 90.27,38.31 90.37,38.41 90.37,38.53 90.5,38.66 90.75,38.66 90.88,38.53 90.88,37.47 91.01,37.34 91.26,37.34 91.39,37.47 91.39,38.33 91.74,38.69 93.55,38.69 95.53,36.71 v2(95.53,36.27)
H_DDR2_D16: length 34.7
  TOP w0.102: U52.L22 v1(69.55,52.45)
  BOTTOM w0.102: 69.34,48.45 69.27,48.53 69.27,48.94 69.34,49.01 69.34,50.6 69.22,50.73 ; 69.75,46.87 69.82,46.79
  BOTTOM w0.127: v1(69.55,52.45) 69.22,52.12 69.22,50.73 ; 69.34,48.45 69.34,47.27 69.75,46.87 ; U116.C7 80.04,29.26 80.04,29.49 80.59,30.05 80.59,32.21 81.05,32.67 81.05,32.95 80.95,33.05 80.82,33.05 80.72,33.15 80.72,33.35 80.82,33.45 80.95,33.45 81.05,33.56 81.05,33.99 80.19,34.85 78.94,34.85 78.82,34.98 78.82,36.27 78.31,36.78 78.31,36.94 78.45,37.08 78.45,37.25 78.33,37.37 78.16,37.37 77.89,37.09 77.74,37.09 77.6,37.24 77.6,37.38 77.89,37.67 77.89,37.84 77.77,37.96 77.6,37.96 77.31,37.67 77.17,37.67 77.02,37.81 77.02,37.96 77.38,38.31 77.38,38.48 77.26,38.6 75.96,38.6 73.33,41.23 73.33,41.51 72.97,41.86 71.07,41.86 69.85,43.08 69.85,46.76 69.82,46.79
H_DDR2_D17: length 33.2
  TOP w0.102: v1(71.12,54.05) U52.K20
  L3-SIGNAL w0.102: 71.58,53.6 71.58,53.11 71.8,52.89 72.16,52.89 72.35,52.69 72.35,51.45 72.59,51.21 72.92,51.21 73.15,50.98 73.15,49.55
  L3-SIGNAL w0.114: v1(71.12,54.05) 71.58,53.6 ; v1(83.43,28.65) 83.82,29.04 83.82,31.35 84.48,32.01 84.48,34.93 84.18,35.23 83.72,35.23 73.23,45.72 73.23,49.47 73.15,49.55
  BOTTOM w0.102: v1(83.43,28.65) U116.C2
H_DDR2_D18: length 33.6
  TOP w0.102: U52.K21 v1(70.36,53.24)
  L3-SIGNAL w0.102: 71.5,50.09 71.14,50.45 70.94,50.45 70.74,50.65 70.74,50.98 70.71,51 70.71,52.88 ; 71.48,46.79 71.48,46.84 71.12,47.2
  L3-SIGNAL w0.114: v1(82.63,29.47) 83.08,29.92 83.08,34.46 76.95,40.59 72.54,40.59 71.15,41.99 71.15,44.53 71.48,44.86 71.48,46.79 ; 71.12,47.2 71.12,47.86 71.5,48.23 71.5,50.09 ; 70.71,52.88 v1(70.36,53.24)
  BOTTOM w0.102: v1(82.63,29.47) U116.B3
H_DDR2_D19: length 35.2
  TOP w0.102: U52.L23 v1(70.33,52.45)
  BOTTOM w0.102: 70.13,47.27 70.13,46.79 ; 69.63,48.56 69.54,48.66 69.54,50.89 69.48,50.95 69.48,51.6
  BOTTOM w0.127: 70.13,46.79 70.13,45.14 70.55,44.71 71.16,44.71 71.41,44.96 73,44.96 73.53,44.43 73.53,44.38 75.36,42.55 75.95,42.55 78.25,40.24 78.25,38.29 78.37,38.17 78.54,38.17 78.84,38.47 79,38.47 79.12,38.35 79.12,38.18 78.79,37.85 78.79,37.72 79.04,37.47 79.04,36.86 79.22,36.68 79.22,35.49 79.4,35.31 80.37,35.31 81.48,34.19 81.48,32.51 80.92,31.96 80.92,29.95 80.42,29.44 80.42,29.06 80.01,28.65 79.44,28.65 U116.C8 ; 70.13,47.27 69.63,47.77 69.63,48.56 ; v1(70.33,52.45) 69.48,51.6
H_DDR2_D20: length 38.6
  TOP w0.102: U52.L24 v1(70.33,51.7)
  BOTTOM w0.102: 70.43,46.79 70.43,47.32 70.05,47.7 ; 69.74,51.31 69.74,48.88 70.05,48.57
  BOTTOM w0.127: 70.43,46.79 70.43,45.95 70.71,45.67 73.08,45.67 74.02,44.73 74.02,44.35 75.54,42.83 76.12,42.83 78.78,40.17 78.78,39.3 78.94,39.13 79.09,39.13 79.24,39.29 79.41,39.29 79.53,39.17 79.53,39 79.38,38.84 79.38,38.7 79.79,38.28 80.26,38.28 80.37,38.18 80.37,37.98 80.26,37.88 79.69,37.88 79.59,37.77 79.59,37.57 79.69,37.47 80.35,37.47 80.47,37.35 80.47,37.18 80.35,37.06 79.69,37.06 79.59,36.96 79.59,36.76 79.69,36.66 80.22,36.66 80.34,36.54 80.34,36.37 80.22,36.25 79.73,36.25 79.6,36.12 79.6,35.84 79.73,35.71 80.59,35.71 81.85,34.46 81.85,32.25 81.29,31.69 81.29,29.86 80.8,29.36 80.8,28.93 80.29,28.43 80.29,28.15 80.01,27.87 79.73,27.87 79.32,27.46 U116.E8 ; v1(70.33,51.7) 70.12,51.49 69.93,51.49 69.74,51.31 ; 70.05,48.57 70.05,48.16 69.91,48.02 69.91,47.85 70.05,47.7
H_DDR2_D21: length 40.2
  TOP w0.102: v1(71.13,52.41) U52.J23
  BOTTOM w0.102: 70.51,51.21 70.14,51.21 69.95,51.02 69.95,50.65 70,50.6 70,49.06 ; 70.69,47.22 70.69,47.78
  BOTTOM w0.127: 70,49.06 70.51,48.55 70.51,47.96 70.69,47.78 ; v1(71.13,52.41) 70.75,52.03 70.75,51.45 70.51,51.21 ; U116.E7 80.04,27.46 80.57,27.99 80.57,28.22 81.18,28.83 81.18,29.29 81.69,29.8 81.69,31.19 82.22,31.73 82.22,32.11 82.4,32.29 82.4,33.91 82.93,34.44 82.93,34.9 82.5,35.33 81.66,35.33 81.23,35.77 81.23,36.15 81.36,36.27 82.5,36.27 82.63,36.4 82.63,36.65 82.5,36.78 81.23,36.78 81.1,36.91 81.1,37.16 81.23,37.29 82.5,37.29 82.63,37.42 82.63,37.67 82.5,37.8 81.08,37.8 80.95,37.92 80.95,38.33 80.57,38.71 80.19,38.71 80.06,38.84 80.06,39.32 76.23,43.16 75.77,43.16 74.42,44.5 74.42,44.88 73.15,46.15 71.75,46.15 70.69,47.22
H_DDR2_D22: length 33.6
  TOP w0.102: v1(71.15,53.25) U52.K22
  L3-SIGNAL w0.114: v1(71.15,53.25) 71.55,52.6 71.55,51.41 71.96,51.01 71.96,50.51 72.28,50.2 72.28,48.75 72.97,48.05 72.97,45.42 83.49,34.9 83.49,29.64 82.25,28.4 v1(81.62,28.4)
  BOTTOM w0.127: U116.E3 82.96,27.54 82.96,27.76 82.45,28.27 82.14,28.27 82.02,28.4 v1(81.62,28.4)
H_DDR2_D23: length 33.5
  TOP w0.102: U52.J20 v1(71.95,54.03)
  L3-SIGNAL w0.102: 73.15,51.84 73.15,51.46 73.36,51.26 73.74,51.26 73.96,51.03 73.96,50.65 73.93,50.62 73.93,49.93 73.57,49.57
  L3-SIGNAL w0.114: v1(71.95,54.03) 72.35,53.47 72.35,53.07 72.64,52.78 72.64,52.35 73.15,51.84 ; 73.57,49.57 73.57,46.09 82.85,36.81 84.23,36.81 84.86,36.17 84.86,30.13 84.63,29.9 84.63,29.07 v1(84.23,28.67)
  BOTTOM w0.102: U116.D2 v1(84.23,28.67)
H_DDR2_D24: length 42.5
  TOP w0.102: 69.88,46.79 70.29,47.2
  TOP w0.127: U68.C7 82.75,28.78 82.52,28.78 82.07,29.24 82.07,29.92 81.99,30 81.99,30.94 82.14,31.09 82.93,31.09 83.03,31.19 83.03,31.39 82.93,31.49 82.08,31.49 81.97,31.61 81.97,32.49 82.07,32.59 83.33,32.59 83.44,32.7 83.44,32.86 83.33,32.97 82.07,32.97 81.97,33.07 81.97,33.25 82.07,33.35 83.33,33.35 83.44,33.46 83.44,33.62 83.33,33.73 81.84,33.73 81.74,33.84 81.74,34.96 82.04,35.26 82.04,35.71 81.38,36.37 81.2,36.37 80.41,35.58 80.27,35.58 80.12,35.73 80.12,35.87 80.99,36.74 80.99,36.92 80.85,37.06 80.7,37.06 80.51,36.87 80.38,36.87 80.09,37.16 80.09,37.41 79.8,37.7 79.62,37.7 79.06,38.26 79.06,38.41 79.41,38.76 79.41,38.9 79.27,39.05 79.13,39.05 78.78,38.69 78.63,38.69 77.93,39.4 77.93,39.6 77.65,39.87 77.29,39.87 77.28,39.86 77.14,39.86 76.5,39.22 75.46,39.22 75.07,38.82 74.82,38.82 74.65,38.99 74.65,39.59 73.83,40.41 73.02,40.41 72.44,41 71.2,41 69.82,42.37 69.82,46.73 69.88,46.79 ; 70.29,47.2 70.29,48.5 U52.L27
H_DDR2_D25: length 37.2
  TOP w0.102: v1(70.39,49.26) U52.L26
  TOP w0.127: v2(82.27,34.42) 83.41,34.42 83.49,34.5 85.67,34.5 86.16,34.01 86.16,33.71 85.75,33.31 85.75,31.71 85.52,31.48 85.32,31.48 85.22,31.38 85.22,31.18 85.32,31.08 86.04,31.08 86.14,30.97 86.14,30.78 86.04,30.67 85.32,30.67 85.22,30.57 85.22,30.37 85.32,30.26 85.52,30.26 85.62,30.16 85.62,28.53 84.96,27.87 84.23,27.87 83.83,27.47 U68.E8
  L3-SIGNAL w0.114: v2(82.27,34.42) 77.69,39 77.66,38.97 77.3,38.97 77.3,38.98 77.14,38.98 76.89,39.23 76.89,39.37 76.17,40.08 72.42,40.08 70.76,41.73 70.76,44.2 70.39,44.57 v1(70.39,49.26)
H_DDR2_D26: length 35
  TOP w0.102: U52.L25 v1(70.44,49.82)
  TOP w0.127: v1(82.63,31.96) 83.64,31.96 83.77,31.83 83.77,31.27 83.44,30.94 83.44,29.45 U68.C8
  L3-SIGNAL w0.114: v1(70.44,49.82) 70.13,49.82 69.98,49.67 69.98,41.89 72.29,39.58 76.02,39.58 77.07,38.53 77.21,38.53 77.34,38.65 77.48,38.65 77.62,38.51 77.62,38.36 77.5,38.24 77.5,38.1 77.64,37.95 77.79,37.95 77.91,38.08 78.05,38.08 78.2,37.93 78.2,37.79 78.08,37.67 78.08,37.52 78.22,37.38 78.36,37.38 78.49,37.5 78.63,37.5 78.77,37.36 78.77,37.21 78.65,37.09 78.65,36.95 78.79,36.8 78.94,36.8 79.06,36.93 79.2,36.93 79.35,36.78 79.35,36.64 79.23,36.52 79.23,36.37 79.37,36.23 79.51,36.23 79.64,36.35 79.78,36.35 79.92,36.21 79.92,36.06 79.8,35.94 79.8,35.8 79.94,35.65 80.09,35.65 80.21,35.78 80.35,35.78 80.5,35.63 80.5,35.49 80.38,35.37 80.38,35.22 80.52,35.08 80.66,35.08 80.79,35.2 80.93,35.2 81.07,35.06 81.07,34.91 80.95,34.79 80.95,34.65 81.09,34.5 81.24,34.5 81.36,34.63 81.5,34.63 81.65,34.48 81.65,34.34 81.53,34.22 81.53,34.07 82.12,33.48 82.42,33.48 82.63,33.28 v1(82.63,31.96)
H_DDR2_D27: length 42.9
  TOP w0.102: 69.55,46.79 69.55,46.88 69.93,47.27
  TOP w0.127: 69.93,47.27 69.93,48.05 ; U68.E3 79.98,27.61 80.16,27.61 80.54,27.99 80.54,28.15 80.87,28.48 81.05,28.48 81.15,28.58 81.15,29.49 81.28,29.62 81.43,29.62 81.56,29.75 81.56,30.76 81.31,31.02 81.31,31.32 81.56,31.57 81.56,32.84 81.2,33.2 81.2,34.04 81.08,34.16 80.85,34.16 80.55,33.87 80.38,33.87 80.26,33.99 80.26,34.16 81.57,35.46 81.57,35.63 81.45,35.75 81.28,35.75 80.19,34.66 80.05,34.66 79.91,34.8 79.91,35.44 79.62,35.73 79.62,35.87 80.1,36.35 80.1,36.52 79.98,36.64 79.81,36.64 79.2,36.03 79.03,36.03 78.92,36.15 78.92,36.32 79.62,37.03 79.62,37.19 79.5,37.31 79.34,37.31 78.75,36.73 78.61,36.73 78.47,36.88 78.47,37.02 79.02,37.58 79.02,37.74 78.9,37.86 78.74,37.86 78.18,37.31 78.04,37.31 77.89,37.45 77.89,37.59 78.37,38.07 78.37,38.24 78.25,38.36 78.08,38.36 77.6,37.88 77.46,37.88 77.32,38.03 77.32,38.17 77.86,38.71 77.86,38.88 77.74,39 77.7,39 77.67,38.97 77.54,38.97 77.03,38.46 76.89,38.46 76.5,38.84 75.59,38.84 75.13,38.38 74.65,38.38 74.32,38.71 74.32,39.4 73.67,40.05 72.94,40.05 72.24,40.74 70.99,40.74 69.55,42.19 69.55,46.79
H_DDR2_D28: length 34.7
  TOP w0.102: v1(68.73,52.41) U52.M23
  TOP w0.127: v1(81.62,29.16) 82.96,27.76 82.96,27.54 U68.E7
  L3-SIGNAL w0.114: v1(81.62,29.16) 81.62,29.83 81.52,29.93 81.17,29.93 81.05,30.05 81.05,30.22 81.17,30.34 81.52,30.34 81.62,30.44 81.62,30.62 81.46,30.78 81.46,31.14 81.62,31.3 81.62,32.65 76.02,38.25 72.34,38.25 69.37,41.23 69.37,48.49 69.52,48.64 69.52,51.61 v1(68.73,52.41)
H_DDR2_D29: length 37.1
  TOP w0.102: 80.24,28.35 80.24,28.12 80.01,27.89 79.4,27.89 ; v1(68.69,50.85) U52.M24
  TOP w0.127: 79.4,27.89 U68.D2 ; 80.24,28.35 80.85,28.96 80.85,29.92 80.92,30 80.92,32.59 v2(79.78,33.73)
  BOTTOM w0.102: 69.02,48.36 69.02,48.98 69.13,49.09 69.13,49.82 69,49.95
  BOTTOM w0.127: 69.02,48.36 69.02,47.08 69.57,46.54 69.57,42.83 71.48,40.92 71.48,40.82 71.99,40.3 72.14,40.3 72.36,40.53 72.53,40.53 72.65,40.41 72.65,40.24 72.42,40.01 72.42,39.87 72.57,39.73 72.71,39.73 72.95,39.97 73.12,39.97 73.24,39.85 73.24,39.68 73,39.44 73,39.3 73.14,39.15 73.29,39.15 73.55,39.42 73.72,39.42 73.84,39.3 73.84,39.13 73.57,38.86 73.57,38.72 73.72,38.58 73.86,38.58 74.15,38.87 74.32,38.87 74.44,38.75 74.44,38.58 74.15,38.29 74.15,38.15 74.29,38 74.44,38 74.73,38.29 74.89,38.29 75.01,38.17 75.01,38 74.79,37.78 74.79,37.5 75.01,37.29 75.77,37.29 75.9,37.16 75.9,36.78 76.02,36.65 76.86,36.65 77.9,35.61 77.9,35.23 77.7,35.03 77.7,34.78 77.9,34.57 77.9,34.44 77.67,34.22 77.67,34.09 77.79,33.98 78.88,33.98 79.12,33.73 v2(79.78,33.73) ; 69,49.95 69,50.54 v1(68.69,50.85)
H_DDR2_D30: length 32.7
  TOP w0.102: U68.B3 79.77,29.86 79.5,30.13 79.5,31.07 79.22,31.35 79.22,32.74 78.61,33.35 78.31,33.35 77.29,34.37 77.29,34.75 ; v1(68.58,49.95) U52.M25
  TOP w0.127: v2(77.29,35.38) 77.29,34.75
  BOTTOM w0.102: v1(68.58,49.95) 68.93,49.6 68.93,49.18 68.81,49.05 68.81,48.71
  BOTTOM w0.127: 68.81,48.71 68.72,48.62 68.72,46.85 69.27,46.31 69.27,42.7 69.85,42.11 69.85,41.81 74.37,37.29 74.37,37.04 74.5,36.91 75.29,36.91 75.41,36.78 75.41,36.25 75.54,36.12 76.36,36.12 76.48,36 76.48,35.83 76.36,35.71 75.62,35.71 75.51,35.61 75.51,35.41 75.62,35.31 76.36,35.31 76.48,35.19 76.48,35.02 76.36,34.9 75.62,34.9 75.51,34.8 75.51,34.57 75.95,34.14 76.76,34.14 77.29,34.67 v2(77.29,35.38)
H_DDR2_D31: length 33
  TOP w0.102: v1(68.55,49.34) U52.M26
  TOP w0.127: v1(79.43,29.45) U68.C2
  BOTTOM w0.127: v1(79.43,29.45) 79.43,32.99 78.79,33.63 74.49,33.63 73.99,34.13 73.99,34.3 74.11,34.42 74.89,34.42 75.01,34.54 75.01,34.71 74.89,34.83 74.09,34.83 73.99,34.93 73.99,35.13 74.09,35.23 74.76,35.23 74.88,35.35 74.88,35.52 74.76,35.64 74.09,35.64 73.99,35.74 73.99,35.94 74.09,36.05 74.76,36.05 74.88,36.16 74.88,36.33 74.76,36.45 74.09,36.45 73.99,36.55 73.99,37.04 69.55,41.48 69.55,41.91 69.01,42.45 69.01,46.05 68.43,46.64 68.43,48.83 68.55,48.95 v1(68.55,49.34)
H_DDR2_DQM0: length 40.7
  TOP w0.127: v2(87.45,37.8) 86.94,37.8 86.82,37.92 86.82,38.38 82.42,42.78 76.61,42.78 73.93,45.45 73.93,48.05
  BOTTOM w0.127: U115.B7 93.78,30.27 93.78,31.3 93.42,31.65 93.42,33.11 93.05,33.48 88.55,33.48 87.97,34.06 87.55,34.06 87.45,34.17 87.45,34.93 87.16,35.22 87.16,35.36 87.99,36.2 87.99,36.37 87.88,36.49 87.71,36.49 86.87,35.65 86.73,35.65 86.58,35.8 86.58,35.94 87.53,36.89 87.53,37.06 87.41,37.18 87.25,37.18 86.29,36.22 86.11,36.22 85.95,36.37 85.95,36.55 86.43,37.03 86.43,37.16 86.18,37.41 86.18,37.67 86.31,37.8 v2(87.45,37.8)
H_DDR2_DQM1: length 44.8
  TOP w0.102: v1(73.58,50.86) U52.G24
  TOP w0.127: U69.B7 96.93,30.32 96.93,30.89 97.99,31.96 97.99,35.82 97.87,35.94 97.28,35.94 97.16,36.07 97.16,36.27 97.28,36.4 97.87,36.4 97.99,36.53 97.99,37.16 97.64,37.52 97.64,38.53 96.09,40.08 94.31,40.08 94.18,39.96 87.96,39.96 v2(84.79,43.13)
  BOTTOM w0.102: 74.73,48.84 74.73,49.45 74.7,49.48 74.7,50.27
  BOTTOM w0.127: 74.7,50.27 74.52,50.45 73.99,50.45 v1(73.58,50.86) ; v2(84.79,43.13) 83.52,43.13 83.41,43.23 83.41,43.74 83.31,43.84 83.11,43.84 83.01,43.74 83.01,43.23 82.91,43.13 82.7,43.13 82.6,43.23 82.6,43.74 82.5,43.84 82.3,43.84 82.19,43.74 82.19,43.23 82.09,43.13 81.86,43.13 81.56,43.44 81.56,44.4 79.87,46.09 79.87,46.78 79.1,47.55 77.65,47.55 77.15,48.05 75.53,48.05 74.73,48.84
H_DDR2_DQM2: length 29.1
  TOP w0.102: U52.K23 v1(71.15,51.64)
  L3-SIGNAL w0.114: v1(71.15,51.64) 71.27,51.51 71.27,51.25 71.58,50.94 71.58,50.45 71.9,50.14 71.9,48.53 72.69,47.73 72.69,45.04 72.36,44.71 71.81,44.71 71.5,44.4 71.5,42.32 71.96,41.86 72.59,41.86 72.72,41.73 v2(72.72,41.35)
  BOTTOM w0.127: v2(72.72,41.35) 75.58,38.5 75.58,38.27 76.61,37.24 76.99,37.24 78.35,35.88 78.35,34.74 78.74,34.34 79.93,34.34 80.31,33.96 80.31,33.38 80.04,33.1 80.04,31.14 80.21,30.97 80.21,30.24 U116.B7
H_DDR2_DQM3: length 34.1
  TOP w0.102: v1(69.55,53.24) U52.M22
  TOP w0.127: v1(82.63,30.25) U68.B7
  L3-SIGNAL w0.102: 69.93,52.86 69.93,51.69
  L3-SIGNAL w0.114: v1(82.63,30.25) 82.22,30.25 82.12,30.36 82.12,30.82 82.22,30.92 82.58,30.92 82.68,31.02 82.68,31.22 82.58,31.32 82.22,31.32 82.12,31.43 82.12,32.84 75.9,39.07 74.18,39.07 74.08,38.97 74.08,38.79 73.98,38.69 73.77,38.69 73.67,38.79 73.67,38.97 73.57,39.07 73.37,39.07 73.27,38.97 73.27,38.79 73.17,38.69 72.96,38.69 72.86,38.79 72.86,38.97 72.76,39.07 72.16,39.07 69.65,41.58 69.65,48.25 69.75,48.35 69.75,51.51 69.93,51.69 ; v1(69.55,53.24) 69.93,52.86
H_DDR2_DQS0: length 49.2
  TOP w0.089: v2(93.8,37.42) 93.57,37.65 93.42,37.65 93.32,37.54 93.32,36.05 92.99,35.71 89.72,35.71 89.45,35.99 89.45,36.74 89.36,36.82 88.97,36.82 88.89,36.74 88.89,35.93 88.61,35.65 88.02,35.65 87.73,35.93 87.73,36.74 87.65,36.82 87.26,36.82 87.18,36.74 87.18,35.93 86.9,35.65 86.21,35.65 85.93,35.93 85.93,38.08 82.08,41.93 81.75,41.93 81.52,41.69 81.07,41.69 80.63,42.13 79.47,42.13 79.24,41.9 78.65,41.9 78.42,42.13 76.19,42.13 76.04,41.98 75.5,41.98 75.07,42.41 75.07,43.4 73.3,45.17 73.3,46.67 73.3,46.68 73.3,46.73 73.23,46.79 73.23,47.31 73.3,47.38 73.3,47.62 73.13,47.79 73.13,48.05
  BOTTOM w0.089: v2(93.8,37.42) 93.54,37.68 93.42,37.68 93.31,37.57 93.31,36.92 93.48,36.74 94.6,36.74 94.92,36.42 94.92,35.61 95.71,34.83 96.6,34.83 96.9,34.83 97.19,34.53 97.19,33.78 96.83,33.41 96.83,32.81 97.19,32.45 97.19,31.84 96.52,31.17 96.52,29.9 96.73,29.69 96.73,29.08 97.06,28.74 97.29,28.74 97.38,28.83 U115.C3
H_DDR2_DQS1: length 50
  TOP w0.089: U52.H27 72.33,48.55 72.47,48.41 72.57,48.41 72.69,48.29 72.69,48.07 72.7,48.06 ; U69.C3 94.33,29.24 94.67,29.24 94.92,29.48 94.92,31.4 94.63,31.69 94.63,32.2 94.92,32.49 94.92,33.15 93.45,34.62 91.82,34.62 91.43,35.01 89.68,35.01 89.4,34.72 89.4,33.25 89.27,33.12 88.95,33.12 88.82,33.25 88.82,34.73 88.54,35.02 87.85,35.02 87.57,34.73 87.57,33.45 87.44,33.33 87.15,33.33 87.02,33.45 87.02,34.83 86.72,35.13 85.35,35.13 85.22,35.26 85.22,37.94 84.86,38.31 83.52,38.31 83.39,38.43 83.39,38.73 83.8,39.14 83.8,39.47 83.36,39.9 83.25,39.9 83.03,39.9 82.4,39.27 82.22,39.27 81.95,39.54 81.95,39.72 81.99,39.76 82.58,40.35 82.58,40.68 82.15,41.11 81.82,41.11 81.41,40.71 81.26,40.71 80.94,41.03 80.64,41.03 80.54,41.13 80.54,41.44 80.3,41.68 79.69,41.68 79.45,41.44 79.45,41 79.25,40.79 78.94,40.79 78.15,41.58 76.41,41.58 75.77,40.95 75.28,40.95 74.3,41.94 74.3,43.72 72.89,45.13 72.89,46.79
  TOP w0.102: 72.89,46.79 72.89,47.65 72.78,47.75 72.78,47.98 72.7,48.06
H_DDR2_DQS2: length 37.2
  TOP w0.089: 71.12,48.16 70.73,48.55 U52.K27 ; 70.66,46.79 70.46,46.59 70.46,42.45 71.02,41.89 72.24,41.89 72.44,42.09 73.24,42.09 73.47,41.86 73.47,41.46 73.73,41.2 73.98,41.2 75.03,40.16 76.28,40.16 76.63,40.52 78.08,40.52 78.81,39.78 79.7,39.78 79.91,39.99 80.56,39.99 80.95,39.6 80.95,39.23 80.39,38.66 80.39,38.48 80.65,38.22 80.83,38.22 81.32,38.7 81.33,38.72 81.7,38.72 82.1,38.32 82.1,37.95 82.08,37.93 81.98,37.83 81.71,37.56 81.71,37.28 81.92,37.07 82.16,37.07 82.5,37.42 83.87,37.42 84.23,37.06 v2(84.23,36.15)
  TOP w0.102: 70.66,46.79 71.12,47.25 71.12,48.16
  BOTTOM w0.089: U116.C3 82.88,28.91 82.42,28.91 82.25,29.09 82.25,29.54 82.18,29.6 82.18,30.42 82.79,31.03 83.12,31.03 83.65,31.56 83.65,32.33 83.37,32.61 83.37,33.1 83.33,33.14 83.33,33.96 83.97,34.6 83.97,35.89 v2(84.23,36.15)
H_DDR2_DQS3: length 41.2
  TOP w0.089: 69.13,47.81 69.13,48.05 ; U68.C3 80.09,29.06 80.23,29.2 80.23,30.99 80.14,31.08 79.91,31.08 79.81,31.19 79.81,31.33 79.91,31.44 80.14,31.44 80.23,31.53 80.23,31.82 80.23,31.82 80.23,31.9 79.7,32.42 79.7,32.83 78.92,33.61 78.59,33.61 78.28,33.91 78.28,34.3 78.5,34.53 79.06,34.53 79.21,34.67 79.21,34.93 79.06,35.08 78.5,35.08 78.24,35.34 78.24,36.04 78.16,36.12 78.09,36.19 77.56,36.19 77.27,36.47 77.27,37.01 76.22,38.06 75.86,38.06 75.6,37.81 75.6,37.43 76.69,36.34 76.69,33.47 76.44,33.21 75.61,33.21 75.35,33.47 75.35,35.75 74.39,36.71 74.39,37.4 74.25,37.54 73.42,37.54 73.06,37.91 73.06,38.31 73.61,38.87 73.61,39.09 73.44,39.26 73.22,39.26 72.94,38.98 72.74,38.78 72.67,38.7 72.3,38.7 71.85,39.16 71.85,39.52 72.04,39.72 72.04,39.98 71.81,40.21 70.67,40.21 69.01,41.87 69.01,46.51 69,46.53 69,46.79
  TOP w0.102: 69,46.79 69,47.14 69.23,47.37 69.23,47.71 69.13,47.81
H_DDR2_DQSN0: length 49.2
  TOP w0.089: U52.G27 73.13,48.55 73.57,48.12 73.57,47.27 73.49,47.2 73.49,46.9 73.57,46.83 ; v2(93.04,38.05) 93.04,36.15 92.89,36 89.82,36 89.71,36.1 89.71,36.85 89.47,37.09 88.86,37.09 88.62,36.85 88.62,36.05 88.5,35.92 88.13,35.92 88,36.05 88,36.85 87.76,37.09 87.15,37.09 86.91,36.85 86.91,36.05 86.79,35.92 86.32,35.92 86.2,36.05 86.2,38.19 82.19,42.19 81.64,42.19 81.41,41.96 81.18,41.96 80.74,42.4 79.36,42.4 79.13,42.17 78.76,42.17 78.53,42.4 76.08,42.4 75.93,42.25 75.61,42.25 75.34,42.52 75.34,43.51 73.57,45.28 73.57,46.79
  TOP w0.102: 73.57,46.79 73.57,46.83
  BOTTOM w0.089: v2(93.04,38.05) 93.04,36.81 93.37,36.48 94.49,36.48 94.65,36.31 94.65,35.5 95.6,34.56 96.79,34.56 96.93,34.42 96.93,33.89 96.56,33.52 96.56,32.7 96.93,32.34 96.93,31.95 96.25,31.28 96.25,29.79 96.46,29.58 96.46,28.97 96.95,28.48 97.17,28.48 U115.D3
H_DDR2_DQSN1: length 50.1
  TOP w0.089: 72.61,46.79 72.61,46.77 72.61,46.77 72.61,46.68 72.62,46.67 72.62,45.02 74.02,43.62 74.02,41.73 75.07,40.68 75.88,40.68 76.52,41.32 78.04,41.32 78.83,40.53 79.36,40.53 79.72,40.89 79.72,41.11 79.72,41.33 79.8,41.42 80.19,41.42 80.27,41.33 80.27,41.02 80.53,40.76 80.83,40.76 81.15,40.44 81.52,40.44 81.93,40.85 82.04,40.85 82.32,40.57 82.32,40.46 82.17,40.31 82.09,40.23 81.83,39.97 81.69,39.83 81.69,39.43 82.11,39.01 82.51,39.01 83.14,39.64 83.25,39.64 83.53,39.36 83.53,39.25 83.28,39 83.12,38.84 83.12,38.69 83.12,38.32 83.4,38.04 84.75,38.04 84.95,37.83 84.95,35.15 85.24,34.86 86.61,34.86 86.75,34.72 86.75,33.34 87.04,33.06 87.55,33.06 87.83,33.34 87.83,34.62 87.96,34.75 88.43,34.75 88.56,34.62 88.56,33.14 88.84,32.86 89.38,32.86 89.66,33.14 89.66,34.61 89.79,34.74 91.32,34.74 91.71,34.36 93.34,34.36 94.65,33.04 94.65,32.6 94.36,32.31 94.36,31.58 94.52,31.42 94.65,31.29 94.65,29.59 94.56,29.5 94.14,29.5 93.83,29.19 93.83,29 U69.D3 ; 72.33,47.8 72.33,48.05
  TOP w0.102: 72.61,46.79 72.61,47.53 72.33,47.8
H_DDR2_DQSN2: length 37.2
  TOP w0.089: 70.84,47.66 70.73,47.76 70.73,48.05 ; v2(83.46,36.15) 83.46,36.53 83.59,36.65 83.87,36.65 83.96,36.75 83.96,36.95 83.76,37.15 82.62,37.15 82.27,36.81 81.81,36.81 81.45,37.17 81.45,37.67 81.79,38.02 81.83,38.06 81.83,38.21 81.59,38.45 81.44,38.45 81.19,38.2 80.94,37.95 80.54,37.95 80.13,38.37 80.13,38.77 80.69,39.34 80.69,39.49 80.45,39.73 80.02,39.73 79.81,39.51 78.7,39.51 77.97,40.25 76.74,40.25 76.39,39.9 74.92,39.9 73.87,40.94 73.62,40.94 73.21,41.35 73.21,41.75 73.14,41.81 72.54,41.81 72.35,41.62 70.91,41.62 70.19,42.34 70.19,46.72 70.26,46.79 ; 70.44,46.97 70.52,47.05
  TOP w0.102: 70.52,47.05 70.52,47.05 70.84,47.37 70.84,47.66 ; 70.26,46.79 70.26,46.79 70.43,46.97 70.44,46.97
  BOTTOM w0.089: U116.D3 82.65,28.64 82.31,28.64 82,28.96 82,29.49 81.92,29.57 81.92,30.53 82.68,31.3 83.01,31.3 83.38,31.67 83.38,32.22 83.11,32.5 83.11,33.1 83.14,33.14 83.14,34.04 83.71,34.6 83.71,35.91 v2(83.46,36.15)
H_DDR2_DQSN3: length 42.2
  TOP w0.089: 69.28,46.79 69.28,41.98 70.78,40.48 71.92,40.48 72.31,40.09 72.31,39.61 72.15,39.45 72.11,39.41 72.11,39.27 72.41,38.97 72.55,38.97 72.67,39.09 72.95,39.37 73.11,39.52 73.31,39.52 73.55,39.52 73.88,39.2 73.88,38.76 73.72,38.6 73.32,38.2 73.32,38.02 73.53,37.81 74.36,37.81 74.66,37.51 74.66,36.82 75.62,35.86 75.62,33.58 75.72,33.48 76.33,33.48 76.43,33.58 76.43,36.23 75.49,37.16 75.34,37.32 75.34,37.92 75.75,38.33 76.33,38.33 76.54,38.12 77.54,37.12 77.54,36.58 77.67,36.45 78.2,36.45 78.35,36.31 78.51,36.15 78.51,35.45 78.62,35.35 78.88,35.35 79.17,35.35 79.28,35.23 79.48,35.04 79.48,34.56 79.17,34.26 78.62,34.26 78.55,34.19 78.55,34.02 78.7,33.87 79.03,33.87 79.97,32.94 79.97,32.53 80.49,32.01 80.49,31.82 80.49,29.09 79.93,28.53 U68.D3
  TOP w0.102: U52.M27 69.55,48.05 69.55,47.79 69.55,47.79 69.55,47.3 69.28,47.03 69.28,46.79
H_DDR2_ODT0: length 86.7
  TOP w0.102: U52.R23 v1(66.37,52.43)
  TOP w0.127: RN3.2 v1(104.3,27) ; U69.G1 92.96,26.24 94.36,26.24 94.58,26.46 94.58,26.84 94.89,27.16 95.96,27.16 96.22,27.41 96.44,27.41 TP2MB3.1 ; TP2MA3.1 82.09,27.41 81.86,27.41 81.61,27.16 80.54,27.16 80.23,26.84 80.23,26.46 80.01,26.24 78.61,26.24 U68.G1
  L3-SIGNAL w0.114: v1(66.37,52.43) 67.11,51.69 67.11,48.67 67.21,48.57 67.21,48.15 67.09,48.04 66.95,48.04 66.84,47.92 66.84,47.7 66.95,47.58 67.09,47.58 67.21,47.47 67.21,46.13 66.7,45.62 66.7,45.24 67.16,44.78 67.16,44.5 66.61,43.96 66.61,42.88 66.74,42.75 67.22,42.75 67.35,42.62 67.35,41.57 67.13,41.35 67.13,40.74 67.26,40.62 67.88,40.62 67.97,40.52 67.97,40.39 67.88,40.29 67.28,40.29 67.18,40.19 67.18,39.99 67.28,39.89 67.79,39.89 67.89,39.78 67.89,39.58 67.79,39.48 67.28,39.48 67.18,39.38 67.18,39.17 67.28,39.07 67.75,39.07 67.87,38.95 67.87,38.79 67.75,38.67 67.28,38.67 67.18,38.56 67.18,37.14 66.88,36.83 66.47,36.83 66.19,36.55 v2(66.19,35.89)
  L6-SIGNAL w0.102: v2(66.19,35.89) 66.47,36.17 67.31,36.17 70.26,33.23 71.53,33.23 74.12,30.63 74.12,30 76.23,27.89 76.23,27.48 77.08,26.62 79.68,26.62 80.14,27.08 81.53,27.08 81.76,27.31 81.99,27.31 TP2MA3.1 82.82,26.94 83.71,26.94 83.97,26.67 85.29,26.67 85.85,27.23 86.84,27.23 87.25,26.82 88.09,26.82 88.45,26.47 89.7,26.47 89.92,26.69 93.14,26.69 93.53,27.08 95.3,27.08 95.38,27 95.86,27 96.14,27.28 96.32,27.28 TP2MB3.1 97.49,26.62 99.61,26.62 99.8,26.8 100.53,26.8 100.66,26.93 101.35,26.93 101.47,26.8 102.08,26.8 102.67,27.38 103.24,27.38 103.62,27 v1(104.3,27)
  BOTTOM w0.127: TP2MA3.1 82.35,27.41 82.35,27.23 82.55,27.03 82.55,26.65 82.93,26.27 84.23,26.27 U116.G1 ; U115.G1 98.58,26.27 97.27,26.27 96.9,26.63 96.9,27.03 96.7,27.23 96.7,27.41 TP2MB3.1
